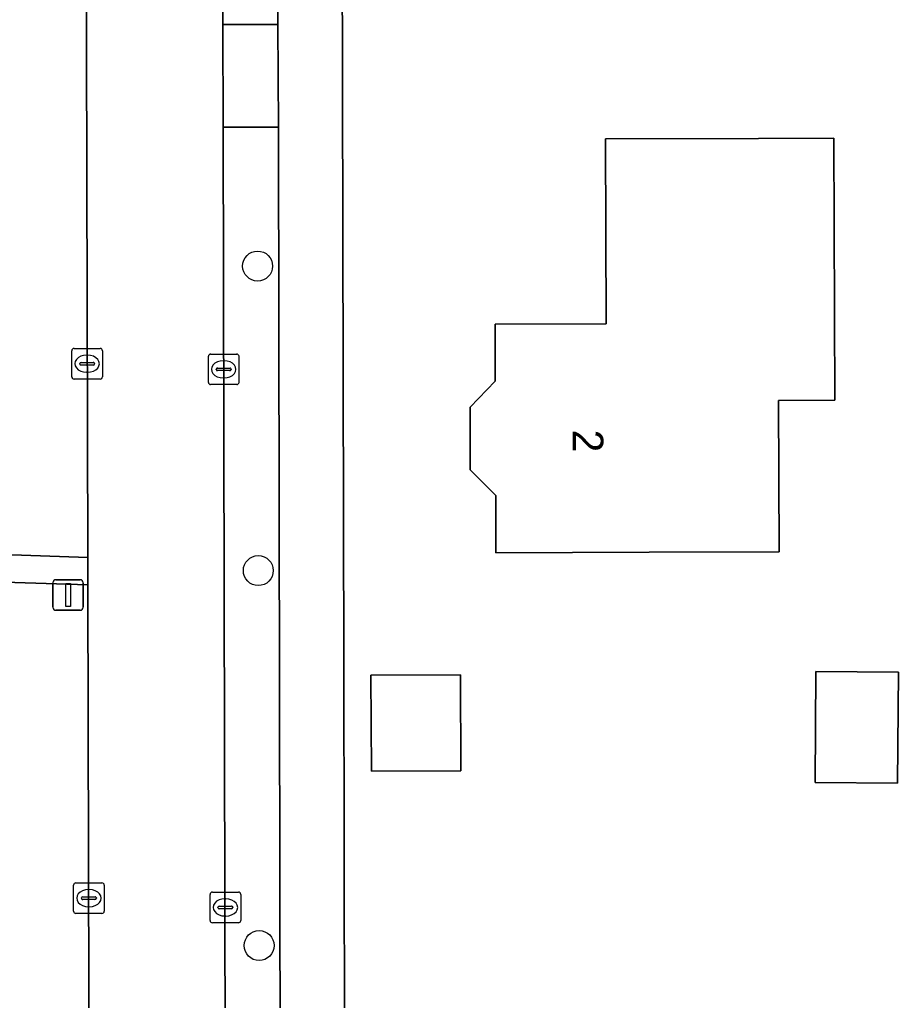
# Model space of a CAD drawing. Extents: x 160455 to 162082, y 388339 to 389736.
# Drawn here: x 160811.08 to 160839.78, y 388409.19 to 388441.23 of the extents above; entities that cross this region are included whole.
import ezdxf

# ---------------------------------------------------------------- set-up
doc = ezdxf.new("R2010")
doc.units = 0
for name, color, linetype in [('IMGEO_Boom', 7, 'Continuous'), ('IMGEO_Erf', 7, 'Continuous'), ('IMGEO_Groenvoorziening', 7, 'Continuous'), ('IMGEO_Kolk', 7, 'Continuous'), ('IMGEO_Lichtmast', 7, 'Continuous'), ('IMGEO_Muur', 7, 'Continuous'), ('IMGEO_Pand', 7, 'Continuous'), ('IMGEO_Pand_nummerreeks', 7, 'Continuous'), ('IMGEO_Parkeervlak_open', 7, 'Continuous'), ('IMGEO_Rijbaan_lokaal_open', 7, 'Continuous'), ('IMGEO_Voetpad_halfverhard', 7, 'Continuous'), ('IMGEO_Voetpad_open', 7, 'Continuous')]:
    doc.layers.add(name, color=color, linetype=linetype)

msp = doc.modelspace()

# ---------------------------------------------------------------- linework, layer by layer
at = {"layer": 'IMGEO_Boom'}
for centre in [(160818.852, 388433.177), (160818.874, 388423.227), (160818.901, 388410.977)]:
    msp.add_circle(centre, 0.489, dxfattribs=at)
at = {"layer": 'IMGEO_Erf'}
msp.add_lwpolyline([(160820.918, 388500), (160820.995, 388498.75), (160821.387, 388490.037), (160821.529, 388481.316), (160821.662, 388420.23), (160821.701, 388401.8), (160821.722, 388392.131)], dxfattribs=at)
for points in [[(160835.212, 388437.345), (160837.666, 388437.351), (160837.697, 388428.795), (160835.863, 388428.789), (160835.88, 388423.843), (160831.636, 388423.828), (160826.636, 388423.811), (160826.626, 388425.684), (160825.796, 388426.524), (160825.796, 388428.57), (160826.614, 388429.414), (160826.606, 388431.278), (160830.232, 388431.288), (160830.212, 388437.333)], [(160837.081, 388419.932), (160839.777, 388419.913), (160839.752, 388416.283), (160837.056, 388416.302)], [(160825.489, 388416.687), (160822.571, 388416.671), (160822.554, 388419.806), (160825.472, 388419.821)]]:
    msp.add_lwpolyline(points, close=True, dxfattribs=at)
at = {"layer": 'IMGEO_Groenvoorziening'}
for points in [[(160765.556, 388452.184), (160765.688, 388448.925), (160765.816, 388446.369), (160766.01, 388441.309), (160766.188, 388433.562), (160766.26, 388429.436), (160766.394, 388426.9), (160768.22, 388426.057), (160771.18, 388426.023), (160778.236, 388425.747), (160785.464, 388425.257), (160793.466, 388424.353), (160813.303, 388423.65), (160813.208, 388461.166), (160813.146, 388463.884), (160813.147, 388481.202)], [(160813.408, 388370.635), (160813.399, 388385.868), (160813.396, 388387.034), (160813.305, 388422.765), (160793.564, 388423.396), (160790.915, 388423.677), (160787.933, 388423.933), (160786.228, 388424.188), (160782.819, 388424.401), (160780.539, 388424.529), (160774.765, 388424.7), (160770.953, 388424.999), (160767.141, 388425.483), (160766.32, 388426.214), (160766.074, 388423.287), (160765.669, 388420.494), (160765.081, 388418.126), (160764.399, 388415.761), (160763.739, 388413.695), (160763.057, 388411.5), (160761.608, 388407.409), (160760.266, 388404.181), (160759.035, 388401.209), (160757.715, 388398.104)]]:
    msp.add_lwpolyline(points, dxfattribs=at)
at = {"layer": 'IMGEO_Kolk'}
for p, q in [((160812.782, 388429.56), (160812.782, 388430.412)), ((160812.857, 388430.486), (160813.709, 388430.486)), ((160813.27, 388430.266), (160813.295, 388430.266)), ((160813.783, 388430.412), (160813.783, 388429.56)), ((160817.242, 388429.377), (160817.242, 388430.229)), ((160817.317, 388430.303), (160818.169, 388430.303)), ((160818.243, 388430.229), (160818.243, 388429.377)), ((160813.041, 388429.98), (160813.041, 388429.992)), ((160813.479, 388429.943), (160813.081, 388429.943)), ((160813.084, 388430.029), (160813.482, 388430.029)), ((160813.525, 388429.992), (160813.525, 388429.98)), ((160817.73, 388430.083), (160817.755, 388430.083)), ((160813.293, 388429.706), (160813.268, 388429.706)), ((160817.501, 388429.797), (160817.501, 388429.809)), ((160817.939, 388429.76), (160817.541, 388429.76)), ((160817.544, 388429.846), (160817.942, 388429.846)), ((160817.985, 388429.809), (160817.985, 388429.797)), ((160813.709, 388429.486), (160812.857, 388429.486)), ((160818.169, 388429.303), (160817.317, 388429.303)), ((160817.753, 388429.523), (160817.728, 388429.523)), ((160812.842, 388412.101), (160812.842, 388412.953)), ((160812.917, 388413.027), (160813.769, 388413.027)), ((160813.843, 388412.953), (160813.843, 388412.101)), ((160813.144, 388412.57), (160813.542, 388412.57)), ((160813.33, 388412.807), (160813.355, 388412.807)), ((160817.298, 388411.797), (160817.298, 388412.649)), ((160817.373, 388412.723), (160818.225, 388412.723)), ((160818.299, 388412.649), (160818.299, 388411.797)), ((160813.101, 388412.521), (160813.101, 388412.533)), ((160813.539, 388412.484), (160813.141, 388412.484)), ((160813.353, 388412.247), (160813.328, 388412.247)), ((160813.585, 388412.533), (160813.585, 388412.521)), ((160817.6, 388412.266), (160817.998, 388412.266)), ((160817.786, 388412.503), (160817.811, 388412.503)), ((160813.769, 388412.027), (160812.917, 388412.027)), ((160817.557, 388412.217), (160817.557, 388412.229)), ((160817.995, 388412.18), (160817.597, 388412.18)), ((160817.809, 388411.943), (160817.784, 388411.943)), ((160818.041, 388412.229), (160818.041, 388412.217)), ((160818.225, 388411.723), (160817.373, 388411.723))]:
    msp.add_line(p, q, dxfattribs=at)
for points in [[(160812.782, 388429.56), (160812.782, 388430.412)], [(160812.857, 388430.486), (160813.709, 388430.486)], [(160813.783, 388430.412), (160813.783, 388429.56)], [(160817.242, 388429.377), (160817.242, 388430.229)], [(160817.317, 388430.303), (160818.169, 388430.303)], [(160818.243, 388430.229), (160818.243, 388429.377)], [(160813.709, 388429.486), (160812.857, 388429.486)], [(160818.169, 388429.303), (160817.317, 388429.303)], [(160812.842, 388412.101), (160812.842, 388412.953)], [(160812.917, 388413.027), (160813.769, 388413.027)], [(160813.843, 388412.953), (160813.843, 388412.101)], [(160817.298, 388411.797), (160817.298, 388412.649)], [(160817.373, 388412.723), (160818.225, 388412.723)], [(160818.299, 388412.649), (160818.299, 388411.797)], [(160813.769, 388412.027), (160812.917, 388412.027)], [(160818.225, 388411.723), (160817.373, 388411.723)]]:
    msp.add_lwpolyline(points, dxfattribs=at)
for centre, radius, start, end in [((160812.859, 388430.41), 0.0765, 91.552, 178.448), ((160812.859, 388430.41), 0.0765, 91.552, 178.448), ((160813.707, 388430.41), 0.0765, 1.552, 88.448), ((160813.707, 388430.41), 0.0765, 1.552, 88.448), ((160817.319, 388430.227), 0.0765, 91.552, 178.448), ((160817.319, 388430.227), 0.0765, 91.552, 178.448), ((160818.167, 388430.227), 0.0765, 1.552, 88.448), ((160818.167, 388430.227), 0.0765, 1.552, 88.448), ((160813.081, 388429.989), 0.0403, 85.8775, 175.7526), ((160813.078, 388429.979), 0.0366, 178.938, 274.7102), ((160813.482, 388429.986), 0.043, 264.8664, 352.4533), ((160813.486, 388429.991), 0.0386, 1.7309, 96.639), ((160812.859, 388429.562), 0.0765, 181.552, 268.448), ((160812.859, 388429.562), 0.0765, 181.552, 268.448), ((160813.707, 388429.562), 0.0765, 271.552, 358.448), ((160813.707, 388429.562), 0.0765, 271.552, 358.448), ((160817.541, 388429.806), 0.0403, 85.8775, 175.7526), ((160817.538, 388429.796), 0.0366, 178.938, 274.7102), ((160817.942, 388429.803), 0.043, 264.8664, 352.4533), ((160817.946, 388429.808), 0.0386, 1.7309, 96.639), ((160817.319, 388429.379), 0.0765, 181.552, 268.448), ((160817.319, 388429.379), 0.0765, 181.552, 268.448), ((160818.167, 388429.379), 0.0765, 271.552, 358.448), ((160818.167, 388429.379), 0.0765, 271.552, 358.448), ((160812.919, 388412.951), 0.0765, 91.552, 178.448), ((160812.919, 388412.951), 0.0765, 91.552, 178.448), ((160813.767, 388412.951), 0.0765, 1.552, 88.448), ((160813.767, 388412.951), 0.0765, 1.552, 88.448), ((160813.141, 388412.53), 0.0403, 85.8775, 175.7526), ((160813.546, 388412.532), 0.0386, 1.7309, 96.639), ((160817.375, 388412.647), 0.0765, 91.552, 178.448), ((160817.375, 388412.647), 0.0765, 91.552, 178.448), ((160818.223, 388412.647), 0.0765, 1.552, 88.448), ((160818.223, 388412.647), 0.0765, 1.552, 88.448), ((160813.138, 388412.52), 0.0366, 178.938, 274.7102), ((160813.542, 388412.527), 0.043, 264.8664, 352.4533), ((160817.597, 388412.226), 0.0403, 85.8775, 175.7526), ((160818.002, 388412.228), 0.0386, 1.7309, 96.639), ((160812.919, 388412.103), 0.0765, 181.552, 268.448), ((160812.919, 388412.103), 0.0765, 181.552, 268.448), ((160813.767, 388412.103), 0.0765, 271.552, 358.448), ((160813.767, 388412.103), 0.0765, 271.552, 358.448), ((160817.594, 388412.216), 0.0366, 178.938, 274.7102), ((160817.998, 388412.223), 0.043, 264.8664, 352.4533), ((160817.375, 388411.799), 0.0765, 181.552, 268.448), ((160817.375, 388411.799), 0.0765, 181.552, 268.448), ((160818.223, 388411.799), 0.0765, 271.552, 358.448), ((160818.223, 388411.799), 0.0765, 271.552, 358.448)]:
    msp.add_arc(centre, radius, start, end, dxfattribs=at)
for centre, major_axis, ratio, start_param, end_param in [((160813.269, 388429.986), (-0.387, 0.002), 0.722429, 4.712389, 7.853982), ((160813.294, 388429.986), (-0.39, 0.002), 0.717154, 1.570796, 4.712389), ((160817.729, 388429.803), (-0.387, 0.002), 0.722429, 4.712389, 7.853982), ((160817.754, 388429.803), (-0.39, 0.002), 0.717154, 1.570796, 4.712389), ((160813.329, 388412.527), (-0.387, 0.002), 0.722429, 4.712389, 7.853982), ((160813.354, 388412.527), (-0.39, 0.002), 0.717154, 1.570796, 4.712389), ((160817.785, 388412.223), (-0.387, 0.002), 0.722429, 4.712389, 7.853982), ((160817.81, 388412.223), (-0.39, 0.002), 0.717154, 1.570796, 4.712389)]:
    msp.add_ellipse(centre, major_axis=major_axis, ratio=ratio, start_param=start_param, end_param=end_param, dxfattribs=at)
at = {"layer": 'IMGEO_Lichtmast'}
for p, q in [((160812.166, 388422.03), (160812.166, 388422.83)), ((160812.166, 388422.83), (160812.166, 388422.03)), ((160812.266, 388422.93), (160813.056, 388422.93)), ((160813.056, 388422.93), (160812.266, 388422.93)), ((160813.156, 388422.83), (160813.156, 388422.03)), ((160813.156, 388422.03), (160813.156, 388422.83)), ((160813.056, 388421.93), (160812.266, 388421.93)), ((160812.266, 388421.93), (160813.056, 388421.93))]:
    msp.add_line(p, q, dxfattribs=at)
msp.add_lwpolyline([(160812.586, 388422.805), (160812.736, 388422.805), (160812.736, 388422.055), (160812.586, 388422.055), (160812.586, 388422.805)], dxfattribs=at)
for centre, start, end in [((160812.266, 388422.83), 90, 180), ((160812.266, 388422.83), 90, 180), ((160813.056, 388422.83), 0, 90), ((160813.056, 388422.83), 360, 90), ((160812.266, 388422.03), 180, 270), ((160812.266, 388422.03), 180, 270), ((160813.056, 388422.03), 270, 0), ((160813.056, 388422.03), 270, 0)]:
    msp.add_arc(centre, 0.1, start, end, dxfattribs=at)
at = {"layer": 'IMGEO_Muur'}
msp.add_lwpolyline([(160821.701, 388401.8), (160821.662, 388420.23)], dxfattribs=at)
at = {"layer": 'IMGEO_Pand'}
for points in [[(160835.212, 388437.345), (160830.212, 388437.333), (160830.232, 388431.288), (160826.606, 388431.278), (160826.614, 388429.414), (160825.796, 388428.57), (160825.796, 388426.524), (160826.626, 388425.684), (160826.636, 388423.811), (160831.636, 388423.828), (160835.88, 388423.843), (160835.863, 388428.789), (160837.697, 388428.795), (160837.666, 388437.351)], [(160837.081, 388419.932), (160837.056, 388416.302), (160839.752, 388416.283), (160839.777, 388419.913)], [(160825.489, 388416.687), (160825.472, 388419.821), (160822.554, 388419.806), (160822.571, 388416.671)]]:
    msp.add_lwpolyline(points, close=True, dxfattribs=at)
at = {"layer": 'IMGEO_Parkeervlak_open'}
for points in [[(160819.458, 388455.485), (160819.458, 388455.624), (160817.683, 388455.62), (160817.715, 388441.066), (160819.513, 388441.07), (160819.512, 388441.308)], [(160819.513, 388441.07), (160817.715, 388441.066), (160817.722, 388437.711), (160819.528, 388437.715)]]:
    msp.add_lwpolyline(points, close=True, dxfattribs=at)
for points in [[(160819.53, 388437.388), (160819.528, 388437.715), (160817.722, 388437.711), (160817.821, 388392.332)], [(160819.608, 388395.042), (160819.53, 388437.388)]]:
    msp.add_lwpolyline(points, dxfattribs=at)
at = {"layer": 'IMGEO_Rijbaan_lokaal_open'}
for points in [[(160817.722, 388437.711), (160817.715, 388441.066), (160817.683, 388455.62), (160817.676, 388458.819), (160817.671, 388461.15), (160813.208, 388461.166), (160813.303, 388423.65), (160813.305, 388422.765), (160813.396, 388387.034)], [(160817.821, 388392.332), (160817.722, 388437.711)]]:
    msp.add_lwpolyline(points, dxfattribs=at)
at = {"layer": 'IMGEO_Voetpad_halfverhard'}
msp.add_lwpolyline([(160793.564, 388423.396), (160813.305, 388422.765), (160813.303, 388423.65), (160793.466, 388424.353)], dxfattribs=at)
at = {"layer": 'IMGEO_Voetpad_open'}
for points in [[(160817.821, 388392.332), (160821.722, 388392.131), (160821.701, 388401.8), (160821.662, 388420.23), (160821.529, 388481.316)], [(160819.406, 388480.535), (160819.408, 388479.965), (160819.419, 388476.834), (160819.42, 388476.606), (160819.461, 388459.411), (160819.461, 388458.823), (160819.458, 388455.624), (160819.458, 388455.485), (160819.512, 388441.308), (160819.513, 388441.07), (160819.528, 388437.715), (160819.53, 388437.388), (160819.608, 388395.042)]]:
    msp.add_lwpolyline(points, dxfattribs=at)

# ---------------------------------------------------------------- texts
at = {"layer": 'IMGEO_Pand_nummerreeks'}
msp.add_text('2', height=1, rotation=270.2302, dxfattribs=at).set_placement((160829.14, 388427.831))

doc.saveas('drawing.dxf')
